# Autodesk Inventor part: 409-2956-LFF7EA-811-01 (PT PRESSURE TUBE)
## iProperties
Created: 2010-09
Part Number: 409-2956-LFF7EA-811-01 (PT PRESSURE TUBE)
Material: 3/8" OD TUBE - SS
Document SubType Name: Modeling
Designer: S. Boerckel
Engineer: Steve Boerckel
Mass: 15.0126 g
Surface Area: 31.4303 cm^2
Volume: 1.85799 cm^3
Density: 8.08 g/cm^3
Description: PT TUBE
Author: S. Boerckel
Revision Number: 0
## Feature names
1. Sweep2
